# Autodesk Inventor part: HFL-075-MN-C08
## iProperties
Created: 2006-08
Part Number: HFL-075-MN-C08
Material: 1.4301 X5CrNi10-10 A2
Document SubType Name: Modellieren
Designer: TMT
Manufacturer: Standard
Standards Organization: Custom
Description: Hohlwelle-Vakuum-Drehdurchführung D=75
Vendor: FERROTEC
Author: TMT
Comments: FERROTEC
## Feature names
1. Extrusion2
2. Extrusion3
3. Extrusion4
4. Bohrung1 [Hole]
5. Bohrung2 [Hole]
6. Runde Anordnung1 [Circular Pattern]
7. Extrusion5
8. Drehung1 [Revolution]
9. Extrusion6
